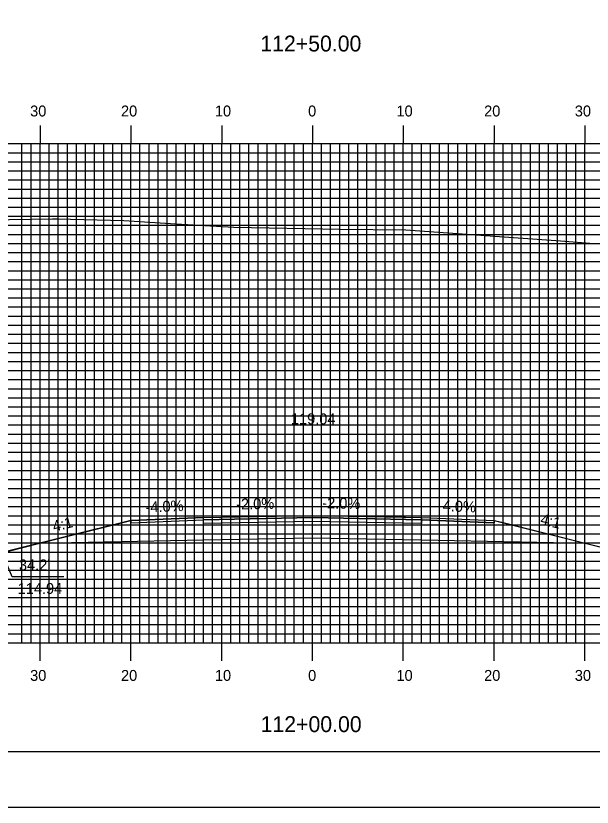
# Model space of a CAD drawing. Extents: x 1770055 to 1770398, y 442591 to 442811.
# Drawn here: x 1770187.9 to 1770251.3, y 442590.5 to 442677.8 of the extents above; entities that cross this region are included whole.
import ezdxf

# ---------------------------------------------------------------- set-up
doc = ezdxf.new("R2010")
doc.units = 0
for name, color, linetype in [('ANNOTATION', 7, 'Continuous'), ('BORDER', 7, 'Continuous'), ('D_Roadway_Centerline', 7, 'Continuous'), ('D_Roadway_Centerline_Text', 7, 'Continuous'), ('D_Roadway_Edge_Shoulder', 7, 'Continuous'), ('D_Roadway_Edge_TW', 7, 'Continuous'), ('D_Roadway_Pavement', 7, 'Continuous'), ('D_Roadway_SlopeLines', 7, 'Continuous'), ('D_Roadway_SubGrade', 7, 'Continuous'), ('H_V ANNOTATION', 7, 'Continuous'), ('MAJOR', 7, 'Continuous'), ('MINOR', 7, 'Continuous'), ('PLOT BOUNDARY', 7, 'Continuous'), ('S_Roadway_Centerline', 7, 'Continuous')]:
    doc.layers.add(name, color=color, linetype=linetype)

msp = doc.modelspace()

# ---------------------------------------------------------------- linework, layer by layer
at = {"layer": 'ANNOTATION'}
msp.add_lwpolyline([(1770193.153, 442615.917), (1770187.461, 442615.917), (1770186.354, 442618.602)], dxfattribs=at)
at = {"layer": 'BORDER'}
msp.add_lwpolyline([(1770070.928, 442596.665), (1770390.928, 442596.665), (1770390.928, 442806.665), (1770070.928, 442806.665)], close=True, dxfattribs=at)
at = {"layer": 'D_Roadway_Centerline'}
msp.add_lwpolyline([(1770129.303, 442654.95), (1770129.452, 442654.939), (1770130.553, 442654.854), (1770130.77, 442654.801), (1770131.803, 442654.548), (1770132.952, 442654.073), (1770133.053, 442654.031), (1770134.303, 442653.303), (1770134.304, 442653.302), (1770162.371, 442634.591), (1770186.354, 442618.602), (1770187.025, 442618.77), (1770190.354, 442619.602), (1770200.03, 442622.022), (1770200.528, 442622.146), (1770208.528, 442622.466), (1770220.528, 442622.706), (1770227.293, 442622.571), (1770232.528, 442622.466), (1770240.528, 442622.146), (1770241.369, 442621.936), (1770250.701, 442619.602), (1770250.702, 442619.602), (1770253.913, 442618.8)], dxfattribs=at)
at = {"layer": 'D_Roadway_Edge_Shoulder'}
for points in [[(1770208.528, 442622.466), (1770200.528, 442622.146), (1770200.528, 442621.896), (1770208.528, 442622.216)], [(1770232.528, 442622.466), (1770240.528, 442622.146), (1770240.528, 442621.896), (1770232.528, 442622.216)]]:
    msp.add_lwpolyline(points, close=True, dxfattribs=at)
at = {"layer": 'D_Roadway_Edge_TW'}
msp.add_lwpolyline([(1770208.528, 442622.216), (1770208.528, 442622.466), (1770220.528, 442622.706), (1770232.528, 442622.466), (1770232.528, 442622.216), (1770220.528, 442622.456)], close=True, dxfattribs=at)
at = {"layer": 'D_Roadway_Pavement'}
msp.add_lwpolyline([(1770208.528, 442621.799), (1770208.528, 442622.216), (1770220.528, 442622.456), (1770232.528, 442622.216), (1770232.528, 442621.799), (1770220.528, 442622.039)], close=True, dxfattribs=at)
at = {"layer": 'D_Roadway_SlopeLines'}
for points in [[(1770200.528, 442622.146), (1770186.354, 442618.602)], [(1770240.528, 442622.146), (1770254.702, 442618.602)]]:
    msp.add_lwpolyline(points, dxfattribs=at)
at = {"layer": 'D_Roadway_SubGrade'}
msp.add_lwpolyline([(1770208.528, 442619.966), (1770190.354, 442619.602), (1770200.528, 442622.146), (1770200.528, 442621.896), (1770208.528, 442622.216), (1770220.528, 442622.456), (1770232.528, 442622.216), (1770240.528, 442621.896), (1770240.528, 442622.146), (1770250.702, 442619.602), (1770232.528, 442619.966), (1770220.528, 442620.206)], close=True, dxfattribs=at)
at = {"layer": 'MAJOR'}
for p, q in [((1770190.528, 442665.669), (1770190.528, 442663.665)), ((1770200.528, 442665.669), (1770200.528, 442663.665)), ((1770210.528, 442665.669), (1770210.528, 442663.665)), ((1770220.528, 442665.669), (1770220.528, 442663.665)), ((1770230.528, 442665.669), (1770230.528, 442663.665)), ((1770240.528, 442665.669), (1770240.528, 442663.665)), ((1770250.528, 442665.669), (1770250.528, 442663.665)), ((1770080.528, 442663.665), (1770360.528, 442663.665)), ((1770080.528, 442663.665), (1770360.528, 442663.665)), ((1770190.528, 442608.665), (1770190.528, 442663.665)), ((1770200.528, 442608.665), (1770200.528, 442663.665)), ((1770210.528, 442608.665), (1770210.528, 442663.665)), ((1770220.528, 442608.665), (1770220.528, 442663.665)), ((1770230.528, 442608.665), (1770230.528, 442663.665)), ((1770240.528, 442608.665), (1770240.528, 442663.665)), ((1770250.528, 442608.665), (1770250.528, 442663.665)), ((1770080.528, 442658.665), (1770360.528, 442658.665)), ((1770080.528, 442653.665), (1770360.528, 442653.665)), ((1770080.528, 442648.665), (1770360.528, 442648.665)), ((1770080.528, 442643.665), (1770360.528, 442643.665)), ((1770080.528, 442638.665), (1770360.528, 442638.665)), ((1770080.528, 442633.665), (1770360.528, 442633.665)), ((1770080.528, 442628.665), (1770360.528, 442628.665)), ((1770080.528, 442623.665), (1770360.528, 442623.665)), ((1770080.528, 442618.665), (1770360.528, 442618.665)), ((1770080.528, 442613.665), (1770360.528, 442613.665)), ((1770080.528, 442608.665), (1770360.528, 442608.665)), ((1770080.528, 442608.665), (1770360.528, 442608.665)), ((1770190.528, 442606.661), (1770190.528, 442608.665)), ((1770200.528, 442606.661), (1770200.528, 442608.665)), ((1770210.528, 442606.661), (1770210.528, 442608.665)), ((1770220.528, 442606.661), (1770220.528, 442608.665)), ((1770230.528, 442606.661), (1770230.528, 442608.665)), ((1770240.528, 442606.661), (1770240.528, 442608.665)), ((1770250.528, 442606.661), (1770250.528, 442608.665))]:
    msp.add_line(p, q, dxfattribs=at)
at = {"layer": 'MINOR'}
for p, q in [((1770188.528, 442608.665), (1770188.528, 442663.665)), ((1770189.528, 442608.665), (1770189.528, 442663.665)), ((1770191.528, 442608.665), (1770191.528, 442663.665)), ((1770192.528, 442608.665), (1770192.528, 442663.665)), ((1770193.528, 442608.665), (1770193.528, 442663.665)), ((1770194.528, 442608.665), (1770194.528, 442663.665)), ((1770195.528, 442608.665), (1770195.528, 442663.665)), ((1770196.528, 442608.665), (1770196.528, 442663.665)), ((1770197.528, 442608.665), (1770197.528, 442663.665)), ((1770198.528, 442608.665), (1770198.528, 442663.665)), ((1770199.528, 442608.665), (1770199.528, 442663.665)), ((1770201.528, 442608.665), (1770201.528, 442663.665)), ((1770202.528, 442608.665), (1770202.528, 442663.665)), ((1770203.528, 442608.665), (1770203.528, 442663.665)), ((1770204.528, 442608.665), (1770204.528, 442663.665)), ((1770205.528, 442608.665), (1770205.528, 442663.665)), ((1770206.528, 442608.665), (1770206.528, 442663.665)), ((1770207.528, 442608.665), (1770207.528, 442663.665)), ((1770208.528, 442608.665), (1770208.528, 442663.665)), ((1770209.528, 442608.665), (1770209.528, 442663.665)), ((1770211.528, 442608.665), (1770211.528, 442663.665)), ((1770212.528, 442608.665), (1770212.528, 442663.665)), ((1770213.528, 442608.665), (1770213.528, 442663.665)), ((1770214.528, 442608.665), (1770214.528, 442663.665)), ((1770215.528, 442608.665), (1770215.528, 442663.665)), ((1770216.528, 442608.665), (1770216.528, 442663.665)), ((1770217.528, 442608.665), (1770217.528, 442663.665)), ((1770218.528, 442608.665), (1770218.528, 442663.665)), ((1770219.528, 442608.665), (1770219.528, 442663.665)), ((1770221.528, 442608.665), (1770221.528, 442663.665)), ((1770222.528, 442608.665), (1770222.528, 442663.665)), ((1770223.528, 442608.665), (1770223.528, 442663.665)), ((1770224.528, 442608.665), (1770224.528, 442663.665)), ((1770225.528, 442608.665), (1770225.528, 442663.665)), ((1770226.528, 442608.665), (1770226.528, 442663.665)), ((1770227.528, 442608.665), (1770227.528, 442663.665)), ((1770228.528, 442608.665), (1770228.528, 442663.665)), ((1770229.528, 442608.665), (1770229.528, 442663.665)), ((1770231.528, 442608.665), (1770231.528, 442663.665)), ((1770232.528, 442608.665), (1770232.528, 442663.665)), ((1770233.528, 442608.665), (1770233.528, 442663.665)), ((1770234.528, 442608.665), (1770234.528, 442663.665)), ((1770235.528, 442608.665), (1770235.528, 442663.665)), ((1770236.528, 442608.665), (1770236.528, 442663.665)), ((1770237.528, 442608.665), (1770237.528, 442663.665)), ((1770238.528, 442608.665), (1770238.528, 442663.665)), ((1770239.528, 442608.665), (1770239.528, 442663.665)), ((1770241.528, 442608.665), (1770241.528, 442663.665)), ((1770242.528, 442608.665), (1770242.528, 442663.665)), ((1770243.528, 442608.665), (1770243.528, 442663.665)), ((1770244.528, 442608.665), (1770244.528, 442663.665)), ((1770245.528, 442608.665), (1770245.528, 442663.665)), ((1770246.528, 442608.665), (1770246.528, 442663.665)), ((1770247.528, 442608.665), (1770247.528, 442663.665)), ((1770248.528, 442608.665), (1770248.528, 442663.665)), ((1770249.528, 442608.665), (1770249.528, 442663.665)), ((1770080.528, 442662.665), (1770360.528, 442662.665)), ((1770080.528, 442661.665), (1770360.528, 442661.665)), ((1770080.528, 442660.665), (1770360.528, 442660.665)), ((1770080.528, 442659.665), (1770360.528, 442659.665)), ((1770080.528, 442657.665), (1770360.528, 442657.665)), ((1770080.528, 442656.665), (1770360.528, 442656.665)), ((1770080.528, 442655.665), (1770360.528, 442655.665)), ((1770080.528, 442654.665), (1770360.528, 442654.665)), ((1770080.528, 442652.665), (1770360.528, 442652.665)), ((1770080.528, 442651.665), (1770360.528, 442651.665)), ((1770080.528, 442650.665), (1770360.528, 442650.665)), ((1770080.528, 442649.665), (1770360.528, 442649.665)), ((1770080.528, 442647.665), (1770360.528, 442647.665)), ((1770080.528, 442646.665), (1770360.528, 442646.665)), ((1770080.528, 442645.665), (1770360.528, 442645.665)), ((1770080.528, 442644.665), (1770360.528, 442644.665)), ((1770080.528, 442642.665), (1770360.528, 442642.665)), ((1770080.528, 442641.665), (1770360.528, 442641.665)), ((1770080.528, 442640.665), (1770360.528, 442640.665)), ((1770080.528, 442639.665), (1770360.528, 442639.665)), ((1770080.528, 442637.665), (1770360.528, 442637.665)), ((1770080.528, 442636.665), (1770360.528, 442636.665)), ((1770080.528, 442635.665), (1770360.528, 442635.665)), ((1770080.528, 442634.665), (1770360.528, 442634.665)), ((1770080.528, 442632.665), (1770360.528, 442632.665)), ((1770080.528, 442631.665), (1770360.528, 442631.665)), ((1770080.528, 442630.665), (1770360.528, 442630.665)), ((1770080.528, 442629.665), (1770360.528, 442629.665)), ((1770080.528, 442627.665), (1770360.528, 442627.665)), ((1770080.528, 442626.665), (1770360.528, 442626.665)), ((1770080.528, 442625.665), (1770360.528, 442625.665)), ((1770080.528, 442624.665), (1770360.528, 442624.665)), ((1770080.528, 442622.665), (1770360.528, 442622.665)), ((1770080.528, 442621.665), (1770360.528, 442621.665)), ((1770080.528, 442620.665), (1770360.528, 442620.665)), ((1770080.528, 442619.665), (1770360.528, 442619.665)), ((1770080.528, 442617.665), (1770360.528, 442617.665)), ((1770080.528, 442616.665), (1770360.528, 442616.665)), ((1770080.528, 442615.665), (1770360.528, 442615.665)), ((1770080.528, 442614.665), (1770360.528, 442614.665)), ((1770080.528, 442612.665), (1770360.528, 442612.665)), ((1770080.528, 442611.665), (1770360.528, 442611.665)), ((1770080.528, 442610.665), (1770360.528, 442610.665)), ((1770080.528, 442609.665), (1770360.528, 442609.665))]:
    msp.add_line(p, q, dxfattribs=at)
at = {"layer": 'PLOT BOUNDARY'}
msp.add_lwpolyline([(1770054.741, 442590.547), (1770394.741, 442590.547), (1770394.741, 442810.547), (1770054.741, 442810.547)], close=True, dxfattribs=at)
at = {"layer": 'S_Roadway_Centerline'}
msp.add_lwpolyline([(1770080.528, 442654.157), (1770085.186, 442654.318), (1770094.979, 442654.295), (1770097.217, 442654.304), (1770100.488, 442654.483), (1770114.303, 442654.9), (1770130.273, 442654.953), (1770131.884, 442654.971), (1770133.085, 442655.012), (1770144.868, 442655.54), (1770153.558, 442655.315), (1770162.971, 442655.45), (1770171.758, 442655.657), (1770179.977, 442655.201), (1770191.894, 442655.367), (1770192.415, 442655.364), (1770199.74, 442655.199), (1770205.48, 442654.814), (1770211.859, 442654.469), (1770223.576, 442654.243), (1770230.798, 442654.178), (1770247.848, 442652.967), (1770251.575, 442652.677)], dxfattribs=at)

# ---------------------------------------------------------------- texts
at = {"layer": 'ANNOTATION'}
for s, rotation, p in [('-4.0%', 2.29062, (1770202.16, 442623.013)), ('-2.0%', 1.14583, (1770212.134, 442623.339)), ('-2.0%', 358.85425, (1770221.596, 442623.485)), ('-4.0%', 357.70938, (1770234.319, 442623.196)), ('4:1', 14.03784, (1770192.063, 442620.891)), ('4:1', 345.96147, (1770245.541, 442621.754))]:
    msp.add_text(s, height=1.2, rotation=rotation, dxfattribs=at).set_placement(p)
for s, p in [("34.2'", (1770188.196, 442616.643)), ('114.94', (1770188.052, 442614.043))]:
    msp.add_text(s, height=1.2, dxfattribs=at).set_placement(p)
at = {"layer": 'D_Roadway_Centerline'}
for s, p in [('C', (1770220.522, 442622.706)), ('L', (1770220.528, 442622.699))]:
    msp.add_text(s, height=0.0146, dxfattribs=at).set_placement(p)
at = {"layer": 'D_Roadway_Centerline_Text'}
msp.add_text('119.04', height=1.2, dxfattribs=at).set_placement((1770218.153, 442632.736))
at = {"layer": 'H_V ANNOTATION'}
for s, height, p in [('112+50.00', 1.75, (1770214.785, 442673.821)), ('30', 1.2, (1770189.425, 442666.665)), ('20', 1.2, (1770199.436, 442666.665)), ('10', 1.2, (1770209.779, 442666.665)), ('0', 1.2, (1770220.046, 442666.665)), ('10', 1.2, (1770229.779, 442666.665)), ('20', 1.2, (1770239.436, 442666.665)), ('30', 1.2, (1770249.425, 442666.665)), ('30', 1.2, (1770189.425, 442604.465)), ('20', 1.2, (1770199.436, 442604.465)), ('10', 1.2, (1770209.779, 442604.465)), ('0', 1.2, (1770220.046, 442604.465)), ('10', 1.2, (1770229.779, 442604.465)), ('20', 1.2, (1770239.436, 442604.465)), ('30', 1.2, (1770249.425, 442604.465)), ('112+00.00', 1.75, (1770214.817, 442598.821))]:
    msp.add_text(s, height=height, dxfattribs=at).set_placement(p)

doc.saveas('drawing.dxf')
